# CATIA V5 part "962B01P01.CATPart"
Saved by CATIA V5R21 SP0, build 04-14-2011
Part number: 962B01P01
Bounding box of the stored display mesh (mm): x -17.1 to 17.1, y -76.2 to 76.2, z -4.4 to 4.4
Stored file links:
  C:\Users\ALI OZGUN\Desktop\alhan\962B01P01.CATPart
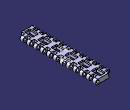
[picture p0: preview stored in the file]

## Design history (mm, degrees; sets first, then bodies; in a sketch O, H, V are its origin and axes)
Body1 (main body)
  Sketch1 on zx-plane, origin (0, 0, 0), H (-1, 0, 0), V (0, 0, 1)
    construction line L1 (-12.7, 0) -> (12.7, 0)
    point P1 (-12.7, 0)
    line L2 (-12.7, 4.4) -> (12.7, 4.4)
    line L3 (12.7, -4.4) -> (-12.7, -4.4)
    arc A1 centre (12.7, 0) radius 4.4 from (12.7, 4.4) to (12.7, -4.4) cw
    arc A2 centre (-12.7, 0) radius 4.4 from (-12.7, -4.4) to (-12.7, 4.4) cw
    distance L1 L2 = 4.4
    length L1 = 25.4
    distance P1 V = 12.7
    coincidence: P1 H
    horizontal: L1 H
    tangency: A1 L2, A2 L2, A1 L3, A2 L3
  Pad1: profile Sketch1, direction (0, 1, 0), length 76.2, mirrored extent
  Sketch2 on face of Pad1 from Sketch1.L2, origin (0, 0, 4.4), H (1, 0, 0), V (0, 1, 0)
    line L1 (-22.3127, -63.5) -> (-9.75, -63.5)
    line L2 (-9.75, -63.5) -> (-9.75, -70.6)
    line L3 (-9.75, -70.6) -> (-22.3127, -70.6)
    line L4 (-22.3127, -70.6) -> (-22.3127, -63.5)
    line L5 (24.6678, -76.95) -> (9.75, -76.95)
    line L6 (9.75, -76.95) -> (9.75, -69.85)
    line L7 (9.75, -69.85) -> (24.6678, -69.85)
    line L8 (24.6678, -69.85) -> (24.6678, -76.95)
    reference projected line E1 (-12.7, -76.2) -> (12.7, -76.2) from edge [start face of Pad1 | face of Pad1 from Sketch1.L2]
    reference projected line E2 (-12.7, -76.2) -> (12.7, -76.2) from edge [start face of Pad1 | face of Pad1 from Sketch1.L2]
    distance L3 E1 = 5.6
    length L4 = 7.1
    distance L7 L5 = 7.1
    distance L5 E2 = 0.75
    distance L2 L6 = 19.5
    distance L2 V = 9.75
    horizontal: L1 H, L3 H, L5 H, L7 H
    vertical: L2 V, L4 V, L6 V, L8 V
  Pocket1: profile Sketch2, direction (0, 0, -1), length 76.2
  RectPattern1: of Pocket1, direction 1 instances 12, spacing 12.7, along axis of face of Pad1 from Sketch1.A2
  Sketch3 on face of Pad1 from Sketch1.L3, origin (0, 0, -4.4), H (1, 0, 0), V (0, -1, 0)
    line L1 (-6.5, -54.6) -> (6.5, -54.6)
    line L2 (6.5, -54.6) -> (6.5, -73.7)
    line L3 (6.5, -73.7) -> (-6.5, -73.7)
    line L4 (-6.5, -73.7) -> (-6.5, -54.6)
    construction line L5 (-4.5, -51.1) -> (4.5, -51.1)
    point P5 (-4.5, -51.1)
    line L6 (-4.5, -49.6) -> (4.5, -49.6)
    line L7 (4.5, -52.6) -> (-4.5, -52.6)
    arc A1 centre (4.5, -51.1) radius 1.5 from (4.5, -49.6) to (4.5, -52.6) cw
    arc A2 centre (-4.5, -51.1) radius 1.5 from (-4.5, -52.6) to (-4.5, -49.6) cw
    reference projected line E1 (12.7, -76.2) -> (-12.7, -76.2) from edge [face of Pad1 from Sketch1.L3 | end face of Pad1]
    distance L5 L6 = 1.5
    distance L1 L3 = 19.1
    distance L4 L2 = 13
    distance L4 V = 6.5
    distance E1 L3 = 2.5
    distance P5 V = 4.5
    length L5 = 9
    distance L7 L1 = 2
    horizontal: L1 H, L3 H, L5 H
    vertical: L2 V, L4 V
    tangency: A1 L6, A2 L6, A1 L7, A2 L7
  Pocket2: profile Sketch3, direction (0, 0, 1), length 6
  RectPattern2: of Pocket2, direction 1 instances 6, spacing 25.8, along axis of face of Pad1 from Sketch1.A2 reversed
  Sketch4 on zx-plane, origin (0, 0, 0), H (-1, 0, 0), V (0, 0, 1)
    circle A1 centre (12.7, 0) radius 2.3
    point P1 (12.7, 0)
    circle A2 centre (-12.7, 0) radius 2.3
    point P2 (-12.7, 0)
    reference projected arc E1 centre (12.7, 0) radius 4.4 from (12.7, -4.4) to (12.7, 4.4) ccw from edge [face of RectPattern1 | face of Pad1 from Sketch1.A1]
    reference projected arc E2 centre (-12.7, 0) radius 4.4 from (-12.7, 4.4) to (-12.7, -4.4) ccw from edge [face of Pad1 from Sketch1.A2 | end face of Pad1]
    radius A1 = 2.3
    radius A2 = 2.3
    coincidence: P1 H, P2 H
    concentricity: P1 E1, A2 E2
  Pocket3: profile Sketch4, direction (0, -1, 0), length 97.8, mirrored extent
  Body2
    Solid1: linked copy from another document
    Symmetry1: Reference yz-plane, ToTransfor Solid1
    Translate1: Direction edge [face of Pocket1 from Sketch2.L2 | face of Pad1 from Sketch1.L3], Length 6.35, ToTransfor Symmetry1
    Body3
      Sketch5 on face of RectPattern1, origin (9.75, 0, 0), H (0, 1, 0), V (0, 0, 1)
      Pad2: profile Sketch5, direction (1, 0, 0), length 12
      Sketch6 on face of Pad2, origin (0, 69.85, 0), H (-1, 0, 0), V (0, 0, 1)
        point P2 (-21.75, 4.4)
        arc A1 centre (-16.4898, 1.5645) radius 9 from (-9.75, -4.4) to (-7.9481, 4.4) ccw
        point P8 (-21.75, 4.4)
        construction line L1 (-9.75, 4.4) -> (-21.75, 4.4)
        line L2 (-7.9481, 4.4) -> (-21.75, 4.4)
        line L3 (-9.75, -4.4) -> (-21.75, -4.4)
        line L4 (-21.75, -4.4) -> (-21.75, 4.4)
        radius A1 = 9
        coincidence: P2 P8
      Pad3: profile Sketch6, direction (0, 1, 0), up to face of Pad2
      RectPattern3: of the body so far, direction 1 instances 12, spacing 12.7, along edge [face of Pad3 | face of Pad3] reversed
    Add1: tool Body3
  Remove1: tool Body2
  Sketch7 on end face of Pocket2, origin (0, 0, 1.6), H (1, 0, 0), V (0, -1, 0)
  Pocket4: profile Sketch7, direction (0, 0, 1), length 6
  RectPattern4: of Pocket4, direction 1 instances 6, spacing 25.8, along axis of face of Pad1 from Sketch1.A2 reversed
  Fillet1: radius 2, on edge [face of Pocket4 | face of Pocket4] (x4); edge [face of RectPattern4 | face of RectPattern4] (x20)
Body4
  Solid2: linked copy from another document
  Translate2: Direction yz-plane, Length 25.4, ToTransfor Solid2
